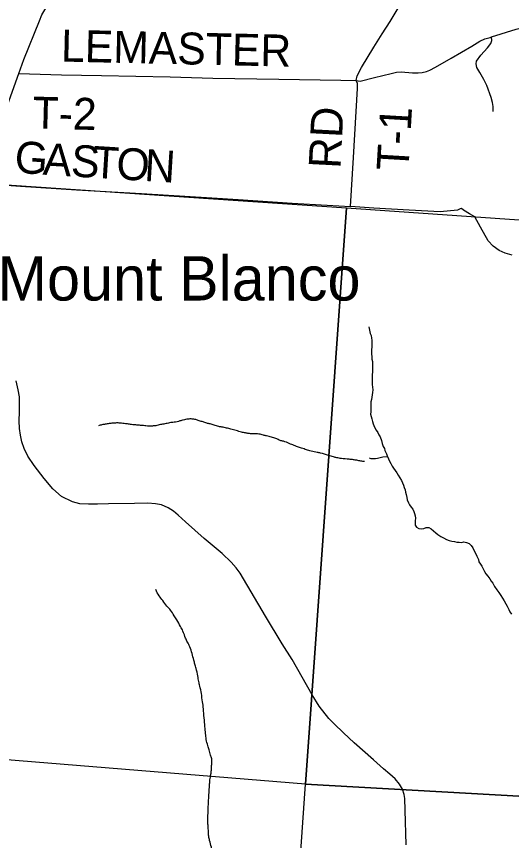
# Model space of a CAD drawing. Extents: x -13.7 to 34, y 0 to 32.3.
# Drawn here: x 28.447 to 29.328, y 18.806 to 20.274 of the extents above; entities that cross this region are included whole.
import ezdxf

# ---------------------------------------------------------------- set-up
doc = ezdxf.new("R2010")
doc.units = 0
for name, color, linetype in [('GM_X_Corporation', 7, 'Continuous'), ('GM_X_Minor_River', 7, 'Continuous'), ('GM_X_State_Route', 7, 'Continuous'), ('GM_X_Township_Road', 7, 'Continuous'), ('GM_X_Township_Road_Text', 7, 'Continuous'), ('GM_X_Unincorporated_Text', 7, 'Continuous')]:
    doc.layers.add(name, color=color, linetype=linetype)

msp = doc.modelspace()

# ---------------------------------------------------------------- linework, layer by layer
at = {"layer": 'GM_X_Corporation'}
for points in [[(28.0076, 20.0028), (29.0337, 19.933), (28.9612, 18.9069), (27.9343, 18.9903)], [(29.0337, 19.933), (30.0496, 19.8628), (29.9735, 18.8499), (28.9612, 18.9069)], [(28.9612, 18.9069), (29.9735, 18.8499), (29.94, 18.4213), (29.9081, 18.0136), (29.8906, 17.8261), (29.334, 17.8585), (28.8921, 17.8887), (28.9044, 18.0795), (28.9355, 18.5389)]]:
    msp.add_lwpolyline(points, close=True, dxfattribs=at)
at = {"layer": 'GM_X_Minor_River'}
for points in [[(29.0735, 19.7214), (29.076, 19.7096), (29.0776, 19.7055), (29.0783, 19.7013), (29.0787, 19.6975), (29.0791, 19.6937), (29.0791, 19.6895), (29.0788, 19.6854), (29.0784, 19.6804), (29.0784, 19.6763), (29.0784, 19.6725), (29.0788, 19.6683), (29.0792, 19.6634), (29.08, 19.6592), (29.08, 19.6554), (29.0804, 19.6509), (29.08, 19.6459), (29.08, 19.6406), (29.0796, 19.6361), (29.0797, 19.6323), (29.0793, 19.6277), (29.0797, 19.6228), (29.0797, 19.6186), (29.0801, 19.6137), (29.0805, 19.6088), (29.0801, 19.6042), (29.0797, 19.6004), (29.079, 19.5962), (29.0782, 19.5917), (29.0775, 19.5879), (29.0771, 19.583), (29.0771, 19.5765), (29.0772, 19.5701), (29.0768, 19.5659), (29.0776, 19.5617), (29.0787, 19.5575), (29.0802, 19.5526), (29.0814, 19.5484), (29.0837, 19.5424), (29.0867, 19.5371), (29.0898, 19.5329), (29.0917, 19.5291), (29.094, 19.525), (29.0959, 19.5189), (29.0974, 19.5136), (29.099, 19.5083), (29.1013, 19.5045), (29.1024, 19.5007), (29.1051, 19.495), (29.1062, 19.4912), (29.1085, 19.4859), (29.1104, 19.4821), (29.1127, 19.4776), (29.1154, 19.4731), (29.1177, 19.4693), (29.1207, 19.4655), (29.1234, 19.4609), (29.1261, 19.4568), (29.1291, 19.4522), (29.1318, 19.4477), (29.1333, 19.4435), (29.1356, 19.439), (29.1368, 19.4352), (29.1383, 19.431), (29.1391, 19.4268), (29.1402, 19.4223), (29.1414, 19.417), (29.1418, 19.4128), (29.1444, 19.4079), (29.1463, 19.4041), (29.149, 19.4003), (29.1517, 19.3965), (29.1536, 19.3924), (29.1551, 19.3886), (29.1559, 19.3844), (29.1567, 19.3802), (29.1563, 19.3757), (29.1563, 19.3719), (29.1563, 19.3681), (29.1582, 19.3643), (29.1628, 19.362), (29.1673, 19.3613), (29.1715, 19.3621), (29.1757, 19.3636), (29.1802, 19.364), (29.1848, 19.3617), (29.189, 19.3576), (29.1928, 19.3542), (29.1966, 19.3511), (29.2019, 19.3477), (29.2065, 19.3451), (29.2118, 19.3424), (29.2168, 19.3406), (29.2213, 19.3394), (29.2263, 19.3387), (29.2304, 19.3379), (29.2342, 19.3379), (29.2384, 19.3372), (29.243, 19.338), (29.2475, 19.3368), (29.2521, 19.335)], [(29.0742, 19.4877), (29.077, 19.4866), (29.0816, 19.4866), (29.0854, 19.4866), (29.0892, 19.487), (29.0937, 19.4882), (29.0986, 19.4897), (29.1067, 19.4901)], [(29.2521, 19.335), (29.2559, 19.3319), (29.2586, 19.3274), (29.2609, 19.3221), (29.2639, 19.3168), (29.2658, 19.3126), (29.2689, 19.3065), (29.2696, 19.3028), (29.2723, 19.2986), (29.2746, 19.2948), (29.2769, 19.2903), (29.2796, 19.2853), (29.2818, 19.2815), (29.2853, 19.277), (29.2887, 19.2721), (29.2914, 19.2683), (29.2944, 19.2645), (29.2975, 19.2588), (29.3017, 19.2528), (29.3051, 19.2482), (29.3085, 19.2429), (29.3116, 19.238), (29.3143, 19.2331), (29.3173, 19.2281), (29.3196, 19.2236), (29.3226, 19.2179), (29.3246, 19.2138), (29.3276, 19.2092)]]:
    msp.add_lwpolyline(points, dxfattribs=at)
for points in [[(29.066, 19.4811), (29.0596, 19.4821), (29.0521, 19.4835), (29.0464, 19.4844), (29.0385, 19.4854), (29.0248, 19.4866), (29.0165, 19.4881), (29.0109, 19.4894), (29.0019, 19.4923), (28.9879, 19.4962), (28.9819, 19.4976), (28.971, 19.4998), (28.9627, 19.502), (28.9541, 19.5053), (28.9466, 19.5075), (28.9409, 19.5099), (28.9319, 19.5133), (28.9218, 19.5174), (28.9158, 19.5187), (28.9083, 19.5224), (28.9004, 19.5246), (28.8918, 19.5271), (28.8861, 19.5281), (28.8782, 19.5302), (28.8665, 19.5306), (28.8597, 19.5312), (28.854, 19.5322), (28.8468, 19.5336), (28.8378, 19.5365), (28.828, 19.5391), (28.8205, 19.5409), (28.8122, 19.5427), (28.8065, 19.5436), (28.7983, 19.5462), (28.7911, 19.5483), (28.7851, 19.5497), (28.7787, 19.5518), (28.7716, 19.5539), (28.7656, 19.556), (28.7592, 19.557), (28.7516, 19.5568), (28.7435, 19.5552), (28.7374, 19.5535), (28.7271, 19.5512), (28.7191, 19.5503), (28.7107, 19.5483), (28.7027, 19.5471), (28.6946, 19.5451), (28.6885, 19.5445), (28.6828, 19.5443), (28.6771, 19.5449), (28.6688, 19.5455), (28.6628, 19.5461), (28.6556, 19.5467), (28.6476, 19.5478), (28.6408, 19.5487), (28.631, 19.5498), (28.6246, 19.55), (28.6177, 19.5495), (28.6116, 19.549), (28.6047, 19.5477), (28.5986, 19.5467), (28.5925, 19.545)], [(28.7058, 18.5154), (28.7095, 18.5177), (28.7168, 18.5198), (28.7255, 18.529), (28.7318, 18.5364), (28.7377, 18.5434), (28.7429, 18.5508), (28.7488, 18.5582), (28.7552, 18.5679), (28.7612, 18.5772), (28.7692, 18.5883), (28.7751, 18.5953), (28.7806, 18.602), (28.7878, 18.6105), (28.7937, 18.6183), (28.7997, 18.6276), (28.8043, 18.6407), (28.8053, 18.6483), (28.8064, 18.6566), (28.8075, 18.6687), (28.8083, 18.6934), (28.808, 18.7059), (28.8072, 18.7158), (28.806, 18.7246), (28.8045, 18.7372), (28.8018, 18.7495), (28.7996, 18.7621), (28.798, 18.772), (28.7961, 18.7819), (28.7935, 18.7942), (28.7904, 18.8064), (28.7888, 18.8137), (28.7883, 18.8213), (28.7875, 18.8335), (28.7874, 18.8419), (28.7874, 18.851), (28.7879, 18.8669), (28.7888, 18.8817), (28.7896, 18.8942), (28.7904, 18.9071), (28.791, 18.9143), (28.7925, 18.9242), (28.7935, 18.9317), (28.7937, 18.9382), (28.7943, 18.9446), (28.7941, 18.9518), (28.7921, 18.9584), (28.7897, 18.9679), (28.7873, 18.9752), (28.7843, 18.9863), (28.7831, 18.9966), (28.782, 19.0092), (28.7806, 19.0248), (28.7792, 19.0408), (28.7778, 19.0534), (28.7756, 19.0679), (28.773, 19.0813), (28.771, 19.0894), (28.7694, 19.0993), (28.7661, 19.1127), (28.764, 19.1204), (28.7624, 19.1273), (28.759, 19.1395), (28.7552, 19.1514), (28.7509, 19.1595), (28.7477, 19.1665), (28.7428, 19.1792), (28.7385, 19.1873), (28.7321, 19.1993), (28.727, 19.2067), (28.7209, 19.2164), (28.7143, 19.2234), (28.7071, 19.2336), (28.7005, 19.2421), (28.6944, 19.2533)], [(28.7426, 18.3371), (28.7453, 18.3604), (28.7453, 18.3703), (28.7447, 18.3767), (28.7446, 18.3836), (28.7449, 18.3931), (28.7439, 18.4091), (28.7419, 18.419), (28.739, 18.4328), (28.7363, 18.4431), (28.734, 18.4535), (28.7302, 18.4665), (28.7271, 18.475), (28.7214, 18.4881), (28.7175, 18.4958), (28.7139, 18.5024), (28.7096, 18.5094), (28.7049, 18.5167), (28.6999, 18.5245), (28.6941, 18.5327), (28.6894, 18.5393), (28.6831, 18.5467), (28.6744, 18.5573), (28.6678, 18.5651), (28.6613, 18.5752), (28.6566, 18.5818), (28.65, 18.5896), (28.6419, 18.5978), (28.6335, 18.6065), (28.6265, 18.6124), (28.6161, 18.6196), (28.6086, 18.624), (28.5982, 18.6304), (28.5907, 18.6337), (28.5826, 18.6393), (28.5762, 18.643), (28.5688, 18.6474), (28.5617, 18.651), (28.5545, 18.6517), (28.5466, 18.6523), (28.5382, 18.6522), (28.5318, 18.6528), (28.5238, 18.6527), (28.5173, 18.6521), (28.5102, 18.6531), (28.5001, 18.6592), (28.4934, 18.6643), (28.486, 18.6691), (28.4797, 18.6735), (28.4731, 18.679), (28.4638, 18.6851), (28.4548, 18.691), (28.4448, 18.6971), (28.4344, 18.7027), (28.4261, 18.7068), (28.4172, 18.7121), (28.4098, 18.7165), (28.4034, 18.7193), (28.3959, 18.7215), (28.3883, 18.7233), (28.3717, 18.7261), (28.3653, 18.7278), (28.3589, 18.7292), (28.3522, 18.7324), (28.3433, 18.7388), (28.3359, 18.7451), (28.3256, 18.7557), (28.3191, 18.7632), (28.3122, 18.7729), (28.3042, 18.7834), (28.2958, 18.7951), (28.2871, 18.8075), (28.2809, 18.8153), (28.2762, 18.8227), (28.2716, 18.8328), (28.2666, 18.8417), (28.2623, 18.849), (28.2581, 18.8583), (28.2519, 18.8684), (28.2469, 18.8761), (28.2422, 18.8846), (28.2379, 18.892), (28.233, 18.9036), (28.2298, 18.9109), (28.2271, 18.9193), (28.2243, 18.927), (28.2222, 18.9343), (28.2203, 18.9435), (28.219, 18.9511), (28.2178, 18.9595), (28.2169, 18.9675), (28.2164, 18.9767)]]:
    msp.add_spline(points, degree=3, dxfattribs=at)
at = {"layer": 'GM_X_State_Route'}
for points in [[(28.4068, 20.0545), (28.4336, 20.1245), (28.451, 20.1726), (28.46, 20.1976), (28.4875, 20.266), (28.4918, 20.2768), (28.4987, 20.2891), (28.5144, 20.3129), (28.5197, 20.3203)], [(29.14, 18.7988), (29.1381, 18.8602), (29.1377, 18.8812), (29.1363, 18.8883), (29.1336, 18.8977), (29.1285, 18.9069), (29.1204, 18.916), (29.1112, 18.9246), (29.0998, 18.9342), (29.0822, 18.9499), (29.0474, 18.9805), (29.0286, 18.9978), (29.0119, 19.0139), (29.0027, 19.0235), (28.9854, 19.0453), (28.9729, 19.0657), (28.937, 19.1288), (28.9195, 19.1563), (28.8895, 19.2061), (28.8446, 19.2823), (28.8373, 19.2921), (28.8289, 19.3019), (28.8124, 19.3176), (28.7806, 19.3444), (28.7475, 19.3737), (28.7343, 19.3856), (28.7263, 19.3931), (28.7167, 19.3988), (28.7047, 19.4039), (28.6943, 19.406), (28.6804, 19.407), (28.6568, 19.4068), (28.6105, 19.4059), (28.5907, 19.4053), (28.5746, 19.4051), (28.5593, 19.4062), (28.5464, 19.4094), (28.5269, 19.4188), (28.5112, 19.4329), (28.4961, 19.451), (28.4779, 19.4745), (28.4669, 19.4908), (28.4602, 19.5043), (28.4563, 19.5165), (28.4536, 19.5285), (28.452, 19.5402), (28.4516, 19.5536), (28.452, 19.5697), (28.4522, 19.5865), (28.4518, 19.5968), (28.4498, 19.6089), (28.4459, 19.6248)]]:
    msp.add_lwpolyline(points, dxfattribs=at)
at = {"layer": 'GM_X_Township_Road'}
for points in [[(29.0512, 20.16), (29.053, 20.1682), (29.0606, 20.1829), (29.0826, 20.2193), (29.0972, 20.243), (29.1115, 20.2649), (29.1662, 20.3566)], [(29.2893, 20.2369), (29.2921, 20.2378), (29.3361, 20.2516), (29.3524, 20.2556), (29.3621, 20.2575), (29.3727, 20.2582), (29.3822, 20.2574), (29.3941, 20.2544), (29.4061, 20.2493), (29.4203, 20.2435), (29.4318, 20.2408), (29.4472, 20.239), (29.4599, 20.2388)], [(29.0512, 20.16), (29.0583, 20.159), (29.0838, 20.1651), (29.1132, 20.1722), (29.1227, 20.1746), (29.1314, 20.1752), (29.1512, 20.1738), (29.1615, 20.1736), (29.1688, 20.174), (29.1761, 20.1758), (29.182, 20.1785), (29.1923, 20.1837), (29.22, 20.1998), (29.2572, 20.2213), (29.2709, 20.2301), (29.2798, 20.2341), (29.2893, 20.2369)], [(29.2948, 20.1046), (29.2948, 20.1137), (29.2935, 20.1206), (29.2911, 20.1295), (29.2834, 20.1511), (29.2782, 20.1617), (29.2711, 20.174), (29.266, 20.1833), (29.2644, 20.1898), (29.2652, 20.1947), (29.2731, 20.205), (29.285, 20.2183), (29.2909, 20.226), (29.2923, 20.2311), (29.2921, 20.2378)], [(28.451, 20.1726), (28.5267, 20.1704), (28.5982, 20.1692), (28.7202, 20.1665), (28.7961, 20.1639), (28.9136, 20.1624), (29.0236, 20.1604), (29.0512, 20.16)], [(28.3778, 19.9772), (28.4538, 19.9719), (28.5533, 19.9651), (28.6689, 19.9588), (28.794, 19.9508), (28.8413, 19.948), (28.9373, 19.9418), (29.0413, 19.9358), (29.0461, 20.023), (29.0533, 20.1455), (29.0533, 20.1547), (29.0512, 20.16)], [(29.2726, 19.8986), (29.2625, 19.9169), (29.2528, 19.9225), (29.2422, 19.9291), (29.2386, 19.9318), (29.2364, 19.9317), (29.2314, 19.9292), (29.2008, 19.926), (29.1452, 19.9292), (29.0823, 19.9324), (29.0413, 19.9358)], [(29.3288, 19.8487), (29.3164, 19.8524), (29.3053, 19.8574), (29.2951, 19.8651), (29.286, 19.8743), (29.2726, 19.8986)]]:
    msp.add_lwpolyline(points, dxfattribs=at)

# ---------------------------------------------------------------- texts
at = {"layer": 'GM_X_Township_Road_Text'}
for s, height, rotation, p in [('LEMASTER', 0.05682, 358.7066, (28.5254, 20.1938)), ('T-2', 0.05682, 358.5687, (28.4747, 20.0746)), ('RD', 0.05682, 87.0658, (29.0232, 20.0022)), ('T-1', 0.05682, 86.6532, (29.144, 19.9981)), ('G', 0.0568, 355.6865, (28.4418, 19.9962)), ('A', 0.0568, 356.4682, (28.4926, 19.9923)), ('S', 0.0568, 356.4771, (28.5425, 19.9893)), ('T', 0.0568, 356.4815, (28.5807, 19.9869)), ('O', 0.0568, 356.4789, (28.6231, 19.9843)), ('N', 0.0568, 356.4814, (28.6731, 19.9812))]:
    msp.add_text(s, height=height, rotation=rotation, dxfattribs=at).set_placement(p)
at = {"layer": 'GM_X_Unincorporated_Text'}
msp.add_text('Mount Blanco', height=0.078977, rotation=0, dxfattribs=at).set_placement((28.413, 19.7681))

doc.saveas('drawing.dxf')
